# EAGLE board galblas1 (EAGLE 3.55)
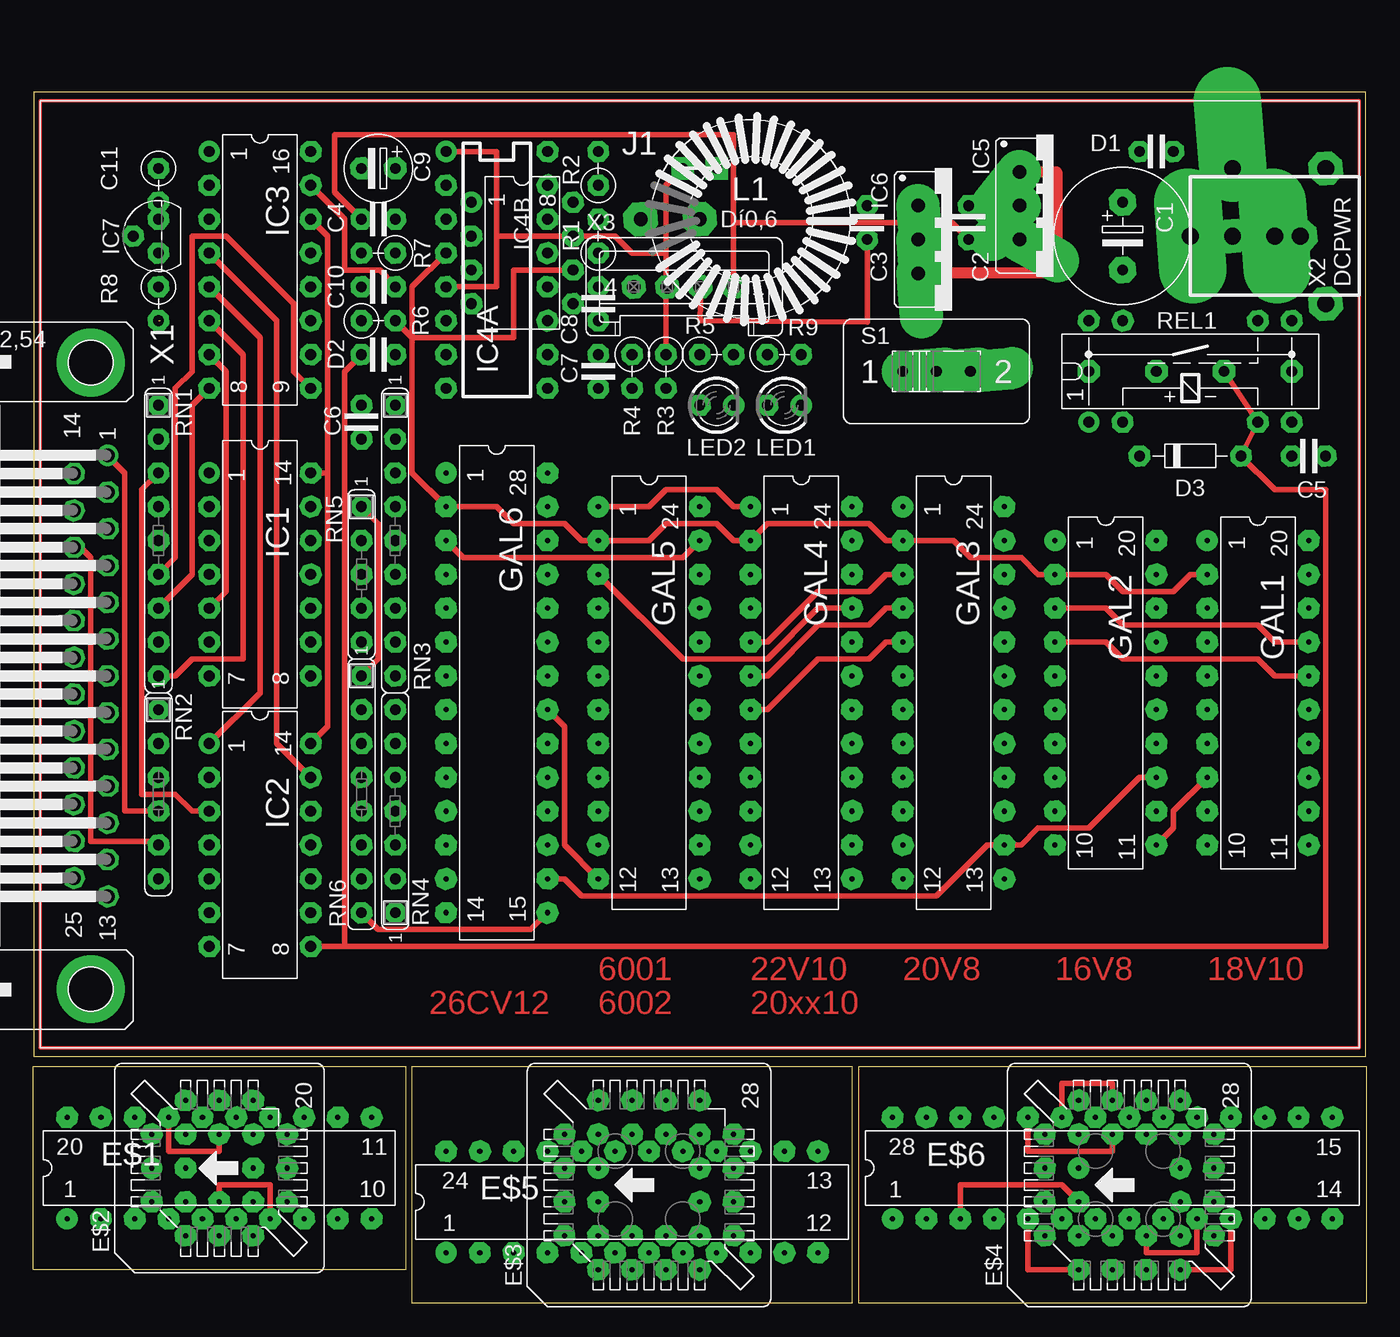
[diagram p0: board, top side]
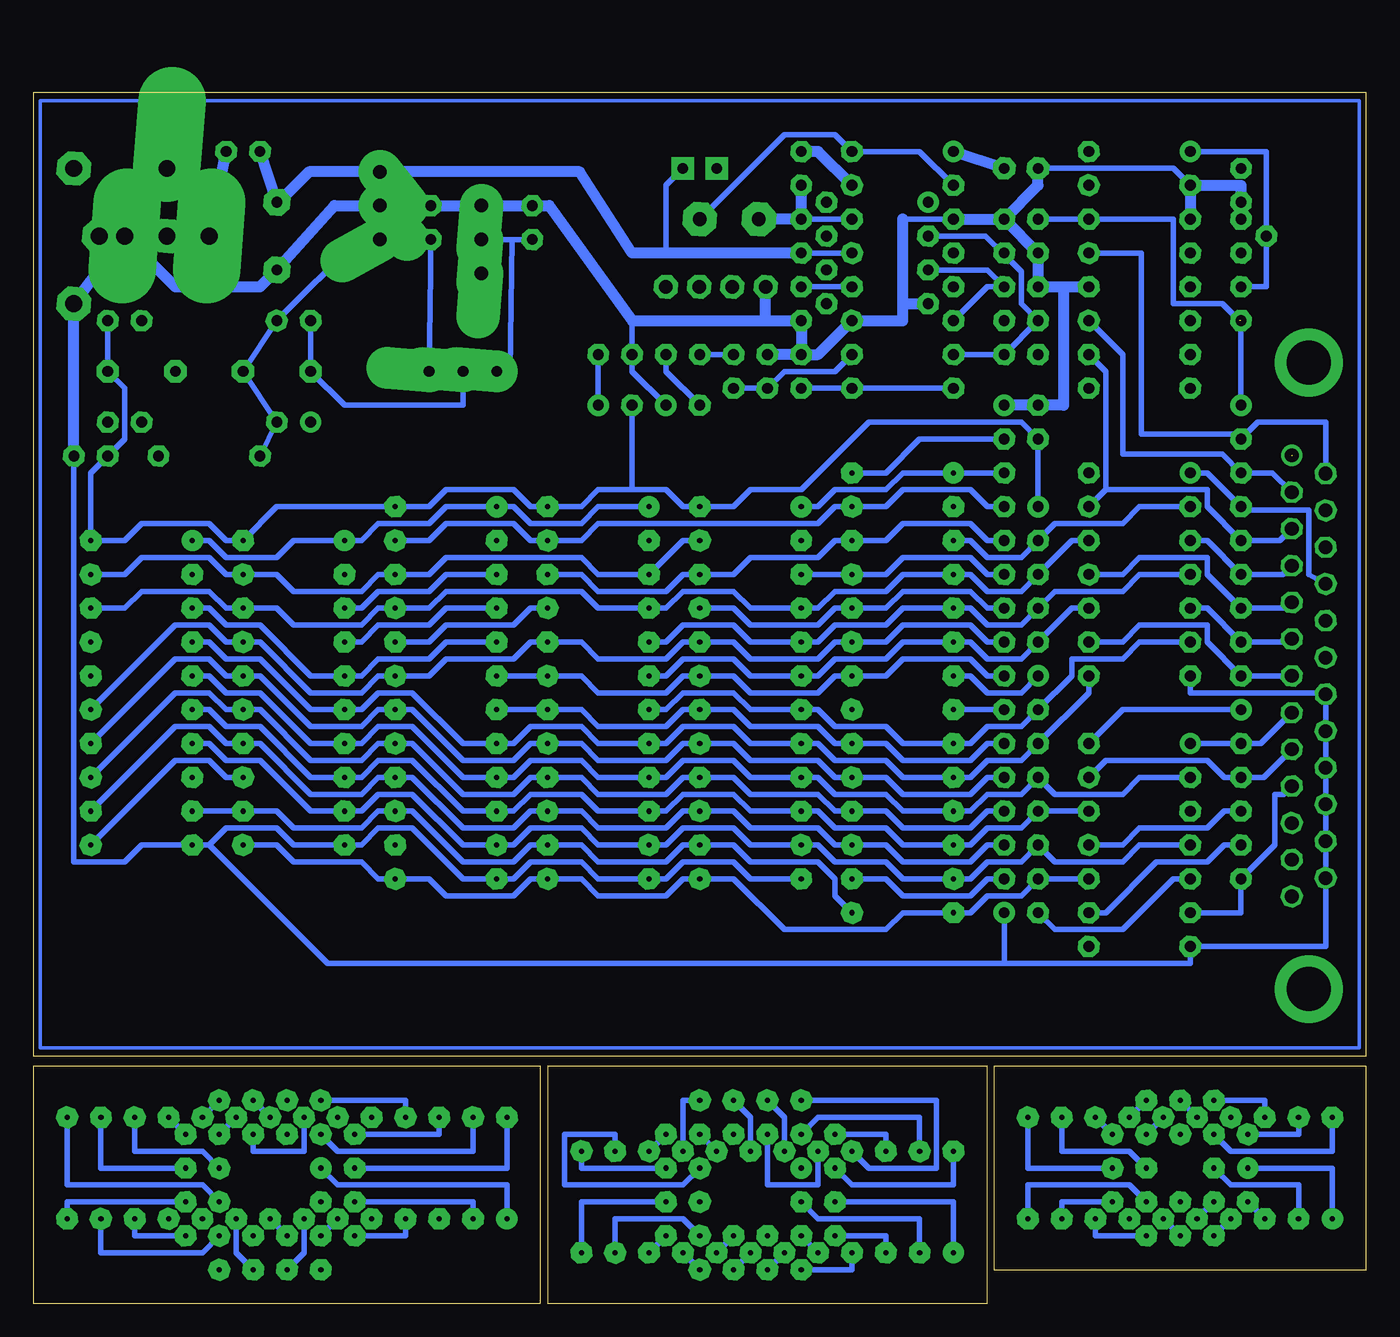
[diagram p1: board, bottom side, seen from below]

Size 100.08 x 90.93 mm. Coordinates in mm from the lower left corner, seen from the top.
Outline: 0.04,18.55 100.04,18.55 100.04,90.93 0.04,90.93 0.04,18.55
Outline: 0,2.54 0,17.78 27.94,17.78 27.94,2.54 0,2.54
Outline: 28.45,0 28.45,17.78 61.47,17.78 61.47,0 28.45,0
Outline: 61.98,0 61.98,17.78 100.08,17.78 100.08,0 61.98,0
Copper layers used: Top, Bottom

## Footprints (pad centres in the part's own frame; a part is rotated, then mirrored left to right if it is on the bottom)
-5 = drill 0.813 pad 2.007 octagon:  -2.54,0;  2.54,0
2,5 = drill 0.813 pad 1.6 octagon:  -1.27,0;  1.27,0
-2,5L = drill 0.813 pad 1.676 octagon:  0,0;  2.54,0
-2,5 = drill 0.813 pad 1.6 octagon:  0,0;  2.54,0
7,5 = drill 0.813 pad 1.6 octagon:  -3.81,0;  3.81,0
L20 = drill 0.381 pad 1.6 round:  -11.43,-3.81 | drill 0.381 pad 1.6 octagon:  -8.89,-3.81;  -6.35,-3.81;  -3.81,-3.81;  -1.27,-3.81;  1.27,-3.81;  3.81,-3.81;  6.35,-3.81;  8.89,-3.81;  11.43,-3.81;  11.43,3.81;  8.89,3.81;  6.35,3.81;  3.81,3.81;  1.27,3.81;  -1.27,3.81;  -3.81,3.81;  -6.35,3.81;  -8.89,3.81;  -11.43,3.81
0 = drill 0.381 pad 1.6 round:  0,5.08 | drill 0.381 pad 1.6 octagon:  0,2.54;  -2.54,5.08;  -5.08,2.54;  -2.54,2.54;  -5.08,0;  -2.54,0;  -5.08,-2.54;  -2.54,-5.08;  -2.54,-2.54;  0,-5.08;  0,-2.54;  2.54,-5.08;  5.08,-2.54;  2.54,-2.54;  5.08,0;  2.54,0;  5.08,2.54;  2.54,5.08;  2.54,2.54
8 = drill 0.381 pad 1.6 round:  1.27,3.81 | drill 0.381 pad 1.6 octagon:  -1.27,6.35;  -1.27,3.81;  -3.81,6.35;  -6.35,3.81;  -3.81,3.81;  -6.35,1.27;  -3.81,1.27;  -6.35,-1.27;  -3.81,-1.27;  -6.35,-3.81;  -3.81,-6.35;  -3.81,-3.81;  -1.27,-6.35;  -1.27,-3.81;  1.27,-6.35;  1.27,-3.81;  3.81,-6.35;  6.35,-3.81;  3.81,-3.81;  6.35,-1.27;  3.81,-1.27;  6.35,1.27;  3.81,1.27;  6.35,3.81;  3.81,6.35;  3.81,3.81;  1.27,6.35
L24-3 = drill 0.381 pad 1.6 round:  -13.97,-3.81 | drill 0.381 pad 1.6 octagon:  -11.43,-3.81;  -8.89,-3.81;  -6.35,-3.81;  -3.81,-3.81;  -1.27,-3.81;  1.27,-3.81;  3.81,-3.81;  6.35,-3.81;  8.89,-3.81;  11.43,-3.81;  13.97,-3.81;  13.97,3.81;  11.43,3.81;  8.89,3.81;  6.35,3.81;  3.81,3.81;  1.27,3.81;  -1.27,3.81;  -3.81,3.81;  -6.35,3.81;  -8.89,3.81;  -11.43,3.81;  -13.97,3.81
L28-3 = drill 0.381 pad 1.6 round:  -16.51,-3.81 | drill 0.381 pad 1.6 octagon:  -13.97,-3.81;  -11.43,-3.81;  -8.89,-3.81;  -6.35,-3.81;  -3.81,-3.81;  -1.27,-3.81;  1.27,-3.81;  3.81,-3.81;  6.35,-3.81;  8.89,-3.81;  11.43,-3.81;  13.97,-3.81;  16.51,-3.81;  16.51,3.81;  13.97,3.81;  11.43,3.81;  8.89,3.81;  6.35,3.81;  3.81,3.81;  1.27,3.81;  -1.27,3.81;  -3.81,3.81;  -6.35,3.81;  -8.89,3.81;  -11.43,3.81;  -13.97,3.81;  -16.51,3.81
L14 = drill 0.813 pad 1.6 round:  -7.62,-3.81 | drill 0.813 pad 1.6 octagon:  -5.08,-3.81;  -2.54,-3.81;  0,-3.81;  2.54,-3.81;  5.08,-3.81;  7.62,-3.81;  7.62,3.81;  5.08,3.81;  2.54,3.81;  0,3.81;  -2.54,3.81;  -5.08,3.81;  -7.62,3.81
L16 = drill 0.813 pad 1.6 round:  -8.89,-3.81 | drill 0.813 pad 1.6 octagon:  -6.35,-3.81;  -3.81,-3.81;  -1.27,-3.81;  1.27,-3.81;  3.81,-3.81;  6.35,-3.81;  8.89,-3.81;  8.89,3.81;  6.35,3.81;  3.81,3.81;  1.27,3.81;  -1.27,3.81;  -3.81,3.81;  -6.35,3.81;  -8.89,3.81
L16' = drill 0.813 pad 1.6 round:  -8.89,-3.81 | drill 0.813 pad 1.6 octagon:  -6.35,-3.81;  -1.27,-3.81;  -3.81,-3.81;  1.27,-3.81;  3.81,-3.81;  6.35,-3.81;  8.89,-3.81;  8.89,3.81;  6.35,3.81;  3.81,3.81;  1.27,3.81;  -1.27,3.81;  -3.81,3.81;  -6.35,3.81;  -8.89,3.81
L08 = drill 0.813 pad 1.6 round:  -3.81,-3.81 | drill 0.813 pad 1.6 octagon:  -1.27,-3.81;  1.27,-3.81;  3.81,-3.81;  3.81,3.81;  1.27,3.81;  -1.27,3.81;  -3.81,3.81
XXS = drill 1.016 pad 3.251 offset:  -2.54,-2.54;  0,-2.54;  2.54,-2.54
220S = drill 1.016 pad 3.251 offset:  -2.54,0;  0,0;  2.54,0
92 = drill 0.813 pad 1.6 octagon:  -1.27,0;  0,1.905;  1.27,0
16 = drill 1.016 pad 2.54 octagon:  -3.81,0;  -8.255,0
D3 = drill 0.813 pad 1.6 octagon:  -1.27,0 | drill 0.813 pad 1.6 round:  1.27,0
1A = drill 0.813 pad 1.6 round:  -7.62,-3.81 | drill 0.813 pad 1.6 octagon:  -5.08,-3.81;  5.08,-3.81;  7.62,-3.81;  7.62,3.81;  5.08,3.81;  -5.08,3.81;  -7.62,3.81
L9 = drill 0.813 pad 1.6 round:  -10.16,0 | drill 0.813 pad 1.6 octagon:  -7.62,0;  -5.08,0;  -2.54,0;  0,0;  2.54,0;  5.08,0;  7.62,0;  10.16,0
L6 = drill 0.813 pad 1.6 round:  -6.35,0 | drill 0.813 pad 1.6 octagon:  -3.81,0;  -1.27,0;  1.27,0;  3.81,0;  6.35,0
L7 = drill 0.813 pad 1.6 round:  -7.62,0 | drill 0.813 pad 1.6 octagon:  -5.08,0;  -2.54,0;  0,0;  2.54,0;  5.08,0;  7.62,0
L5 = drill 0.813 pad 1.6 round:  -5.08,0 | drill 0.813 pad 1.6 octagon:  -2.54,0;  0,0;  2.54,0;  5.08,0
L8 = drill 0.813 pad 1.6 round:  -8.89,0 | drill 0.813 pad 1.6 octagon:  -6.35,0;  -3.81,0;  -1.27,0;  1.27,0;  3.81,0;  6.35,0;  8.89,0
51 = drill 0.813 pad 3.15 offset:  -2.54,0;  0,0;  2.54,0
5HP = drill 1.016 pad 1.6 octagon:  16.561,1.27;  13.792,1.27;  11.049,1.27;  8.28,1.27;  5.512,1.27;  2.769,1.27;  0,1.27;  -2.769,1.27;  -5.512,1.27;  -8.28,1.27;  -11.049,1.27;  -13.792,1.27;  15.189,-1.27;  12.421,-1.27;  9.652,-1.27;  6.909,-1.27;  4.14,-1.27;  1.372,-1.27;  -1.372,-1.27;  -4.14,-1.27;  -6.909,-1.27;  -9.652,-1.27;  -12.421,-1.27;  -15.189,-1.27 | drill 1.016 pad 1.6 round:  -16.561,1.27 | drill 3.302 pad 5.08 round:  -23.52,0;  23.52,0
PWR = drill 1.27 pad 2.54 octagon:  -5.08,-7.62;  5.08,-7.62;  0,-0.635;  0,-5.715 | drill 1.27 pad 5.08 offset:  5.08,-0.635 | drill 1.27 pad 5.08 long:  0,2.54;  0,-3.81
4P = drill 1.016 pad 1.778 octagon:  -4.978,0;  -7.493,0;  -2.489,0;  0,0

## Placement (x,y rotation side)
C1  470u/16V  [-5]  81.79,80.14 270 top
C2  100n  [2,5]  70.23,81.15 270 top
C3  100n  [2,5]  62.61,81.15 270 top
C4  100n  [2,5]  25.91,81.41 180 top
C5  100n  [2,5]  95.76,63.63 180 top
C6  100n  [2,5]  24.64,66.17 270 top
C7  100n  [2,5]  42.42,69.98 90 top
C8  10n  [2,5]  42.42,75.06 270 top
C9  100u/35V  [-2,5L]  27.18,85.22 180 top
C10  4n7  [2,5]  25.91,76.33 180 top
C11  1u/3V  [-2,5]  9.4,85.22 270 top
D1  1N4001  [2,5]  84.33,86.49 180 top
D2  1N4148  [2,5]  25.91,71.25 0 top
D3  1N4148  [7,5]  86.87,63.63 180 top
E$1  [L20]  13.97,10.16 0 top
E$2  [0]  13.97,10.16 90 top
E$3  [8]  46.23,8.89 90 top
E$4  [8]  82.3,8.89 90 top
E$5  [L24-3]  44.96,7.62 0 top
E$6  [L28-3]  81.03,10.16 0 top
GAL1  18V10  [L20]  91.95,45.85 270 top
GAL2  16V8  [L20]  80.52,45.85 270 top
GAL3  20V8  [L24-3]  69.09,45.85 270 top
GAL4  22V10/20xx10  [L24-3]  57.66,45.85 270 top
GAL5  6001/6002  [L24-3]  46.23,45.85 270 top
GAL6  26CV12  [L28-3]  34.8,45.85 270 top
IC1  7417  [L14]  17.02,54.74 270 top
IC2  7417  [L14]  17.02,34.42 270 top
IC3  TLC7524JN  [L16]  17.02,77.6 270 top
IC4A  78S40  [L16']  34.8,77.6 270 top
IC4B  CA3140E  [L08]  36.7,78.87 270 top
IC5  7805  [XXS]  76.58,82.42 270 top
IC6  LD1117V33  [220S]  66.42,79.88 270 top
IC7  LM336Z2.5  [92]  9.4,80.14 90 top
L1  470uH  [16]  53.85,81.41 0 top
LED1  LED3YE  [D3]  56.39,67.44 0 top
LED2  LED3GR  [D3]  51.31,67.44 0 top
R1  1R2  [-2,5]  42.42,78.87 90 top
R2  180R  [-2,5]  42.42,83.95 90 top
R3  220k  [-2,5]  47.5,71.25 270 top
R4  12k  [-2,5]  44.96,71.25 270 top
R5  4k7  [-2,5]  50.04,71.25 0 top
R6  100k  [-2,5]  24.64,73.79 0 top
R7  12k  [-2,5]  27.18,78.87 180 top
R8  390R  [-2,5]  9.4,76.33 270 top
R9  820R  [-2,5]  55.12,71.25 0 top
REL1  RR1A  [1A]  86.87,69.98 0 top
RN1  4k7  [L9]  9.4,57.28 270 top
RN2  4k7  [L6]  9.4,38.23 270 top
RN3  4k7  [L9]  27.18,57.28 270 top
RN4  4k7  [L7]  27.18,36.96 90 top
RN5  4k7  [L5]  24.64,54.74 270 top
RN6  4k7  [L8]  24.64,38.23 270 top
S1  SW1  [51]  67.82,69.98 0 top
X1  M25HP  [5HP]  4.32,47.12 270 top
X2  DCPWR  [PWR]  89.41,80.14 90 top
X3  S04P  [4P]  52.58,76.33 0 top

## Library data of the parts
C1-C11 D1-D3 R1-R9 = DISCRETE
E$1 E$5 E$6 GAL1-GAL6 = DIL
E$2-E$4 = PLCCPACK
IC1 IC2 = 74XX
IC3 IC4B IC7 = LINEAR
IC4A IC5 = V-REG
IC6 = manfred
L1 = IND-A
LED1 LED2 = LED
REL1 = RELAIS
RN1-RN6 = R-SIL
S1 = SWITCH
X1 = SUBD-A
X2 = SPECIAL
X3 = CON-MT

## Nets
/ACK: IC2. RN2. X1.
/STB: GAL1. GAL2. GAL3. GAL4. GAL5. GAL6. IC2. RN6.
/STROBE: IC2. RN2. X1.
D0: IC2. IC3. RN1. X1.
D1: IC1. IC3. RN1. X1.
D2: IC1. IC3. RN1. X1.
D3: IC1. IC3. RN1. X1.
D4: IC1. IC3. RN1. X1.
D5: IC1. IC3. RN1. X1.
D6: IC2. IC3. RN2. X1.
D7: IC2. IC3. RN2. X1.
EDIT: GAL1. GAL2. GAL3. GAL4. GAL5. GAL6. IC4A. IC4B. R6.
N$1: IC3. RN1. X1.
N$2: D1. X2.
N$3: IC1. RN1. X1.
N$4: IC2. RN2. X1.
N$5: C7. IC4A.
N$6: LED2. R5.
N$7: C8. IC4A.
N$8: REL1. S1.
N$9: GAL6. RN4.
N$10: GAL3. GAL4. GAL5. GAL6. RN3.
N$11: IC4A. R3. R4.
N$12: LED1. R9.
N$13: IC4A. L1. R1. R2.
N$14: IC4A. R2.
N$15: GAL5. GAL6. RN3.
N$16: GAL1. GAL2. GAL3. GAL4. GAL5. GAL6. RN3.
N$17: IC4A. L1.
N$18: C9. IC4A. IC4B. R3. R5. X3.
N$19: C1. C2. C3. C4. C5. C6. C7. C8. C9. C10. C11. GAL1. GAL2. GAL3. GAL4. GAL5. GAL6. IC1. IC2. IC3. IC4A. IC4B. IC5. IC6. IC7. LED2. R4. R7. R9. RN3. RN4. X1. X2. X3.
N$20: C1. D1. IC4A. IC5. IC6. R1.
N$21: C11. IC3. IC7. R8.
N$22: GAL3. GAL4. GAL5. GAL6. RN3.
N$23: D2. IC4A. IC4B. R6. R7.
N$24: GAL3. GAL4. GAL5. GAL6. RN4.
N$25: GAL1. GAL2. GAL3. GAL4. GAL5. GAL6. RN4.
N$26: GAL1. GAL2. GAL3. GAL4. GAL5. GAL6. RN4.
N$27: C2. C4. D3. IC1. IC2. IC3. IC5. R8. REL1. RN1. RN2. S1. X3.
N$28: GAL1. GAL2. GAL3. GAL4. GAL5. GAL6. RN4.
N$29: GAL1. GAL2. GAL3. GAL6. RN4.
N$30: GAL6. RN3.
N$31: GAL1. GAL2. GAL3. GAL4. GAL5. GAL6. RN3.
N$32: GAL4. GAL5. GAL6. RN3.
N$33: GAL3. GAL4. GAL6. RN3.
N$35: C10. IC3. IC4A. IC4B.
N$39: D2. D3. IC2. REL1.
P/V: GAL1. GAL2. GAL3. GAL4. GAL5. GAL6. IC1. RN5.
RA0: GAL1. GAL2. GAL3. GAL4. GAL5. GAL6. IC1. RN5.
RA1: GAL1. GAL2. GAL3. GAL4. GAL5. GAL6. IC1. RN5.
RA2: GAL1. GAL2. GAL3. GAL4. GAL5. GAL6. IC1. RN5.
RA3: GAL1. GAL2. GAL3. GAL4. GAL5. GAL6. IC1. RN6.
RA4: GAL1. GAL2. GAL3. GAL4. GAL5. GAL6. IC1. RN6.
RA5: GAL1. GAL2. GAL3. GAL4. GAL5. GAL6. IC2. RN6.
S$1: E$1. E$2.
S$2: E$1. E$2.
S$3: E$1. E$2.
S$4: E$1. E$2.
S$5: E$1. E$2.
S$6: E$1. E$2.
S$7: E$1. E$2.
S$8: E$4. E$6.
S$9: E$4. E$6.
S$10: E$1. E$2.
S$11: E$1. E$2.
S$12: E$1. E$2.
S$13: E$1. E$2.
S$14: E$1. E$2.
S$15: E$1. E$2.
S$16: E$1. E$2.
S$17: E$1. E$2.
S$18: E$1. E$2.
S$19: E$1. E$2.
S$20: E$1. E$2.
S$21: E$1. E$2.
S$22: E$1. E$2.
S$24: E$4. E$6.
S$25: E$4. E$6.
S$26: E$4. E$6.
S$27: E$4. E$6.
S$28: E$4. E$6.
S$29: E$4. E$6.
S$30: E$4. E$6.
S$31: E$4. E$6.
S$32: E$4. E$6.
S$33: E$4. E$6.
S$34: E$4. E$6.
S$35: E$4. E$6.
S$36: E$4. E$6.
S$37: E$4. E$6.
S$38: E$4. E$6.
S$39: E$4. E$6.
S$40: E$4. E$6.
S$41: E$4. E$6.
S$42: E$3. E$5.
S$43: E$3. E$5.
S$44: E$3. E$5.
S$45: E$3. E$5.
S$46: E$3. E$5.
S$47: E$3. E$5.
S$48: E$3. E$5.
S$49: E$3. E$5.
S$50: E$3. E$5.
S$51: E$3. E$5.
S$52: E$3. E$5.
S$53: E$3. E$5.
S$54: E$3. E$5.
S$55: E$3. E$5.
S$56: E$3. E$5.
S$57: E$3. E$5.
S$58: E$3. E$5.
S$59: E$3. E$5.
S$60: E$3. E$5.
S$61: E$3. E$5.
S$62: E$3. E$5.
S$63: E$3. E$5.
S$64: E$3. E$5.
S$65: E$3. E$5.
S$66: E$4. E$6.
S$67: E$4. E$6.
S$68: E$4. E$6.
S$69: E$4. E$6.
S$70: E$4. E$6.
S$71: E$4. E$6.
S$72: E$4. E$6.
S$73: E$4. E$6.
SCHALT: X2.
SCLK: GAL1. GAL2. GAL3. GAL4. GAL5. GAL6. IC2. RN6.
SDIN: GAL1. GAL2. GAL3. GAL4. GAL5. GAL6. IC2. RN6.
SDOUT: GAL1. GAL2. GAL3. GAL4. GAL5. GAL6. IC2. RN6.
SW1: C3. IC6. S1. X3.
VCC: C5. C6. GAL1. GAL2. GAL3. GAL4. GAL5. GAL6. LED1. REL1. RN5. RN6.

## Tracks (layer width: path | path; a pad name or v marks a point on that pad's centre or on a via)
/ACK
  Bottom 0.406: 5.59,38.84 6.2,38.23 6.86,38.23 6.86,34.42 RN2. 9.4,29.34 13.21,29.34
/STB
  Top 0.406: 88.14,39.5 85.6,36.96 85.6,35.69 84.33,34.42
  Bottom 0.406: 84.33,34.42 81.79,34.42 80.52,33.15 75.44,33.15 74.17,31.88 72.9,31.88 70.36,31.88 69.09,30.61 64.01,30.61 62.74,31.88 61.47,31.88 58.93,31.88 57.66,30.61 52.58,30.61 51.31,31.88 50.04,31.88 47.5,31.88 43.69,28.07 36.07,28.07 34.8,29.34 30.99,29.34 29.72,29.34 28.45,30.61 25.91,30.61 24.64,31.88 20.83,31.88
/STROBE  (1 unrouted)
  Top 0.406: 5.59,63.63 6.86,62.36 6.86,36.96 9.4,36.96
  Bottom 0.406: 9.4,36.96 10.67,36.96 11.94,35.69 17.02,35.69 18.29,34.42 20.83,34.42
D0
  Top 0.406: 9.4,62.36 8.13,61.09 8.13,38.23 10.67,38.23 11.94,36.96 13.21,36.96
  Bottom 0.406: 5.59,60.91 7.04,62.36 9.4,62.36 10.8,63.75 18.29,63.75 18.29,71.25 20.83,73.79
D1
  Bottom 0.406: 5.59,58.17 6.48,57.28 9.4,57.28 11.94,59.82 11.94,61.09 19.56,61.09 | 19.56,61.09 20.83,59.82 | 19.56,61.09 19.56,69.98 20.83,71.25
D2
  Top 0.406: 20.83,68.71 19.56,69.98 19.56,75.06 14.48,80.14 11.94,80.14 11.94,69.98 10.67,68.71 10.67,56.01 9.4,54.74
  Bottom 0.406: 5.59,55.4 6.25,54.74 9.4,54.74 11.94,57.28 13.21,57.28
D3
  Top 0.406: 13.21,68.71 11.94,67.44 11.94,54.74 9.4,52.2
  Bottom 0.406: 5.59,52.63 6.02,52.2 9.4,52.2 11.94,54.74 11.94,56.01 17.02,56.01 18.29,54.74 20.83,54.74
D4
  Top 0.406: 13.21,71.25 14.48,69.98 14.48,53.47 13.21,52.2
  Bottom 0.406: 5.59,49.89 5.82,49.66 9.4,49.66 11.94,52.2 13.21,52.2
D5
  Top 0.406: 13.21,73.79 15.75,71.25 15.75,48.39 11.94,48.39 10.67,47.12 RN1.
  Bottom 0.406: 5.59,47.12 RN1. 11.94,49.66 11.94,50.93 17.02,50.93 18.29,49.66 20.83,49.66
D6
  Top 0.406: 13.21,76.33 17.02,72.52 17.02,45.85 13.21,42.04
  Bottom 0.406: 5.59,44.35 7.9,42.04 9.4,42.04 13.21,42.04
D7
  Top 0.406: 13.21,78.87 18.29,73.79 18.29,42.04 20.83,39.5
  Bottom 0.406: 5.59,41.61 7.7,39.5 9.4,39.5 10.67,39.5 11.94,40.77 19.56,40.77 20.83,39.5
EDIT
  Top 0.406: 88.14,54.74 86.87,54.74 85.6,53.47 81.79,53.47 80.52,54.74 76.71,54.74 75.44,54.74 74.17,56.01 70.36,56.01 69.09,57.28 65.28,57.28 64.01,57.28 62.74,58.55 55.12,58.55 53.85,57.28 52.58,57.28 51.31,58.55 47.5,58.55 46.23,57.28 42.42,57.28 41.15,57.28 39.88,58.55 36.07,58.55 34.8,59.82 30.99,59.82 28.45,62.36 28.45,72.52 | 40.51,77.6 36.07,77.6 36.07,72.52 28.45,72.52 | 28.45,72.52 R6. | 30.99,78.87 28.45,76.33 28.45,72.52
N$1
  Bottom 0.406: 3.05,62.31 3.05,66.17 8.13,66.17 9.4,64.9 9.78,65.28 16.89,65.28 16.89,78.87 20.83,78.87
N$2
  Bottom 0.813: 85.6,86.49 86.87,80.14 89.41,80.14
N$3
  Bottom 0.406: 3.05,54.03 4.32,54.74 4.32,59.56 9.14,59.56 9.4,59.82 11.94,62.36 13.21,62.36
N$4
  Top 0.406: 3.05,56.77 3.56,56.77 4.32,56.01 4.32,34.67 9.14,34.67 9.4,34.42
  Bottom 0.406: 9.4,34.42 10.67,34.42 11.94,33.15 15.75,33.15 19.56,29.34 20.83,29.34
N$5
  Bottom 0.406: 30.99,68.71 38.61,68.71 42.42,68.71
N$6
  Bottom 0.406: 50.04,67.44 52.58,69.98 R5.
N$7
  Bottom 0.406: 38.61,76.33 42.42,76.33
N$8  (via drill 0.81 pad 1.68)
  Bottom 0.406: 67.82,69.98 67.82,67.44 76.71,67.44 v79.25,69.98 REL1.
N$9
  Bottom 0.406: RN4. 30.99,44.58
N$10
  Top 0.406: 61.47,52.2 58.93,52.2 55.12,48.39 48.77,48.39 42.42,54.74
  Bottom 0.406: 42.42,54.74 38.61,54.74 36.07,54.74 34.8,56.01 29.72,56.01 28.45,54.74 27.18,54.74 | 61.47,52.2 62.74,52.2 64.01,50.93 69.09,50.93 70.36,49.66 72.9,49.66
N$11
  Bottom 0.406: 38.61,71.25 39.88,69.98 43.69,69.98 R4. R3.
N$12
  Bottom 0.406: LED1. R9.
N$13
  Bottom 0.406: 38.61,81.41 R1.
  Bottom 0.813: 42.42,83.95 R1. L1.
N$14
  Bottom 0.813: 38.61,83.95 41.15,86.49 R2.
N$15
  Bottom 0.406: 50.04,52.2 47.5,52.2 46.23,50.93 41.15,50.93 39.88,52.2 38.61,52.2 36.07,52.2 34.8,53.47 29.72,53.47 28.45,52.2 27.18,52.2
N$16
  Bottom 0.406: 27.18,49.66 28.45,49.66 29.72,50.93 34.8,50.93 36.07,49.66 38.61,49.66 39.88,49.66 41.15,48.39 46.23,48.39 47.5,49.66 50.04,49.66 51.31,49.66 52.58,48.39 57.66,48.39 58.93,49.66 61.47,49.66 62.74,49.66 64.01,48.39 69.09,48.39 70.36,47.12 72.9,47.12 74.17,47.12 75.44,45.85 79.25,45.85 83.06,49.66 84.33,49.66 85.6,49.66 86.87,50.93 89.41,50.93 95.76,44.58
N$17
  Bottom 0.406: 30.99,83.95 33.53,86.49 IC4A. 39.88,87.76 43.69,87.76 50.04,81.41
N$18  (via drill 0.81 pad 1.68)
  Top 0.406: 47.5,76.33 47.5,71.25 | 47.5,76.33 47.6,76.33 | 47.5,78.87 47.5,76.33 | 47.5,78.87 44.96,78.87 43.69,80.14 40.51,80.14 34.8,80.14 | 34.8,80.14 34.8,86.49 30.99,86.49 | 47.5,78.87 47.5,83.95 v48.77,85.22 | 30.99,76.33 34.8,76.33 34.8,80.14
  Bottom 0.406: 47.5,71.25 50.04,71.25
  Bottom 0.813: 30.99,86.49 27.18,85.22
N$19
  Top 0.406: 38.61,44.58 39.88,43.31 39.88,34.42 42.42,31.88
  Bottom 0.406: 42.42,31.88 46.23,31.88 47.5,33.15 51.31,33.15 52.58,31.88 53.85,31.88 57.66,31.88 58.93,33.15 62.74,33.15 64.01,31.88 65.28,31.88 67.82,31.88 71.63,35.69 74.17,35.69 75.44,34.42 76.71,34.42 80.52,34.42 81.79,35.69 85.6,35.69 86.87,34.42 | 24.64,67.44 27.18,67.44 | 86.87,34.42 88.14,34.42 91.95,34.42 93.22,33.15 97.03,33.15 97.03,63.63 | 27.18,25.53 13.21,25.53 13.21,26.8 3.05,26.8 3.05,31.93 3.05,34.7 3.05,36.96 | 13.21,47.12 13.21,45.85 3.05,45.85 3.05,45.74 3.05,42.98 3.05,40.21 | 27.18,25.53 27.18,29.34 | 27.18,25.53 77.98,25.53 86.87,34.42 | 34.8,81.41 30.99,81.41 | 55.12,73.79 55.12,71.25 55.12,69.98 LED2. | 3.05,36.96 3.05,37.47 3.05,39.5 | 3.05,40.21 3.05,40.77 | 3.05,39.5 3.05,40.21 | 3.05,36.96 3.05,39.5 | 3.05,36.96 3.05,40.21 | 13.21,83.95 14.48,85.22 C9. | C8. C7. C8.
  Bottom 0.813: 70.23,82.42 74.04,82.42 70.23,82.42 | 70.23,82.42 77.47,82.42 C1. 83.06,76.33 89.41,76.33 93.22,80.14 97.03,75.06 97.03,63.63 | C7. 41.15,71.25 38.61,73.79 34.8,73.79 34.8,75.06 | 34.8,75.06 34.8,81.41 | C7. C8. 44.96,73.79 | C7. 44.96,71.25 | 27.18,67.44 24.64,67.44 22.73,67.44 22.73,76.33 | 44.96,73.79 55.12,73.79 61.34,82.42 62.61,82.42 66.42,82.42 70.23,82.42 | 45.09,76.33 45.09,73.91 44.96,73.79 | 13.21,81.41 13.21,83.95 9.4,83.95 IC7. | 34.8,75.06 32.89,75.06 | 30.99,81.41 27.18,81.41 | 22.73,76.33 C10. R7. 27.18,81.41 | 27.18,81.41 24.64,83.95 C9. | 22.73,76.33 20.83,76.33
N$20  (via drill 0.81 pad 1.68)
  Top 0.813: IC6. 76.83,77.34 76.83,84.96 74.04,84.96
  Bottom 0.406: 38.61,78.87 42.42,78.87 | 52.58,78.87 52.58,83.95 v51.31,85.22
  Bottom 0.813: 42.42,78.87 52.58,78.87 55.12,78.87 59.05,84.96 74.04,84.96 79.38,84.96 81.66,82.68 81.79,82.68 D1.
N$21
  Bottom 0.406: 13.21,86.49 9.4,86.49 7.49,86.49 7.49,80.14 7.49,76.33 9.4,76.33
N$22
  Bottom 0.406: 65.28,47.12 61.47,47.12 58.93,47.12 57.66,45.85 52.58,45.85 51.31,47.12 50.04,47.12 47.5,47.12 46.23,45.85 41.15,45.85 39.88,47.12 38.61,47.12 36.07,47.12 34.8,48.39 29.72,48.39 28.45,47.12 RN3.
N$23
  Bottom 0.406: 30.99,71.25 D2. 24.64,73.79 25.91,75.06 25.91,77.47 27.18,78.74 | 27.18,78.74 27.18,78.87 | 32.89,80.14 28.57,80.14 27.18,78.74
N$24
  Bottom 0.406: 65.28,44.58 61.47,44.58 58.93,44.58 57.66,43.31 52.58,43.31 51.31,44.58 50.04,44.58 47.5,44.58 46.23,43.31 41.15,43.31 39.88,42.04 38.61,42.04 36.07,42.04 34.8,40.77 29.72,40.77 28.45,42.04 27.18,42.04
N$25
  Bottom 0.406: 27.18,39.5 28.45,39.5 29.72,38.23 34.8,38.23 36.07,39.5 38.61,39.5 39.88,39.5 41.15,40.77 46.23,40.77 47.5,42.04 50.04,42.04 51.31,42.04 52.58,40.77 57.66,40.77 58.93,42.04 61.47,42.04 62.74,42.04 64.01,40.77 67.82,40.77 71.63,44.58 72.9,44.58 74.17,44.58 75.44,43.31 79.25,43.31 83.06,47.12 84.33,47.12 85.6,47.12 86.87,48.39 89.41,48.39 95.76,42.04
N$26
  Bottom 0.406: 27.18,36.96 28.45,36.96 29.72,35.69 34.8,35.69 36.07,36.96 38.61,36.96 39.88,36.96 41.15,38.23 46.23,38.23 47.5,39.5 50.04,39.5 51.31,39.5 52.58,38.23 57.66,38.23 58.93,39.5 61.47,39.5 62.74,39.5 64.01,38.23 67.82,38.23 71.63,42.04 72.9,42.04 74.17,42.04 75.44,40.77 79.25,40.77 83.06,44.58 84.33,44.58 85.6,44.58 86.87,45.85 89.41,45.85 95.76,39.5
N$27  (via drill 0.81 pad 1.68)  (1 unrouted)
  Top 0.406: C4. 22.61,83.44 22.61,87.76 52.58,87.76 52.58,81.15 | 52.58,81.15 X3. | C2. 68.96,81.15 52.58,81.15 | 22.1,62.36 22.1,43.31 IC2. | 22.1,62.36 IC1. | 22.1,62.36 22.1,80.14 20.83,81.41
  Bottom 0.406: 9.52,73.79 10.8,75.06 14.48,75.06 14.48,81.41 20.83,81.41 C4. | IC2. 18.29,44.58 9.4,44.58 | C2. IC5. | C2. 70.23,77.34 S1. | C2. IC5. | D3. 81.79,66.17 v84.33,69.98 81.79,73.79 75.69,79.88 IC5. | 9.4,67.44 R8.
N$28
  Bottom 0.406: 27.18,34.42 28.45,34.42 29.72,33.15 34.8,33.15 36.07,34.42 38.61,34.42 39.88,34.42 41.15,35.69 46.23,35.69 47.5,36.96 50.04,36.96 51.31,36.96 52.58,35.69 57.66,35.69 58.93,36.96 61.47,36.96 62.74,36.96 64.01,35.69 67.82,35.69 71.63,39.5 72.9,39.5 74.17,39.5 75.44,38.23 79.25,38.23 83.06,42.04 84.33,42.04 85.6,42.04 86.87,43.31 89.41,43.31 95.76,36.96
N$29
  Top 0.406: 38.61,31.88 39.88,31.88 41.15,30.61 67.82,30.61 71.63,34.42 72.9,34.42 74.17,34.42 75.44,35.69 79.25,35.69 83.06,39.5 84.33,39.5
  Bottom 0.406: 38.61,31.88 36.07,31.88 34.8,30.61 29.72,30.61 28.45,31.88 27.18,31.88 | 95.76,34.42 89.41,40.77 86.87,40.77 85.6,39.5 84.33,39.5
N$30
  Bottom 0.406: GAL6. 36.07,62.36 33.53,64.9 27.18,64.9
N$31
  Top 0.406: 42.42,59.82 46.23,59.82 47.5,61.09 51.31,61.09 52.58,59.82 53.85,59.82
  Bottom 0.406: 42.42,59.82 41.15,59.82 39.88,61.09 36.07,61.09 34.8,62.36 30.99,62.36 27.18,62.36 | 88.14,57.28 86.87,57.28 85.6,56.01 81.79,56.01 80.52,57.28 76.71,57.28 75.44,57.28 74.17,58.55 70.36,58.55 69.09,59.82 65.28,59.82 64.01,59.82 62.74,58.55 58.93,58.55 57.66,59.82 53.85,59.82
N$32
  Bottom 0.406: 61.47,54.74 58.93,54.74 57.66,53.47 52.58,53.47 51.31,54.74 50.04,54.74 47.5,54.74 46.23,56.01 41.15,56.01 39.88,57.28 38.61,57.28 36.07,57.28 34.8,58.55 29.72,58.55 28.45,57.28 27.18,57.28
N$33
  Bottom 0.406: 72.9,57.28 70.36,57.28 69.09,58.55 64.01,58.55 62.74,57.28 61.47,57.28 58.93,57.28 57.66,58.55 41.15,58.55 39.88,59.82 38.61,59.82 36.07,59.82 34.8,61.09 29.72,61.09 28.45,59.82 27.18,59.82
N$34
  Top 0.254: 0.51,90.3 99.57,90.3 99.57,19.18 0.51,19.18 0.51,90.3
N$35
  Top 0.406: 20.83,83.95 23.37,81.41 23.37,77.6 26.04,77.6 26.42,77.22 27.18,76.33
  Bottom 0.406: 32.89,77.6 28.45,77.6 27.18,76.33 28.45,76.33 30.99,73.79
N$37
  Bottom 0.254: 0.51,90.3 99.57,90.3 99.57,19.18 0.51,19.18 0.51,90.3
N$38  (via drill 0.81 pad 1.68)
  other vias: 94.49,69.98
N$39  (via drill 0.81 pad 1.68)
  Top 0.406: 20.83,26.8 23.37,26.8 | 23.37,26.8 23.37,69.98 24.64,71.25 | 23.37,26.8 97.03,26.8 97.03,61.09 93.22,61.09 90.68,63.63 91.95,66.17 v89.41,69.98
P/V
  Top 0.406: 50.04,57.28 48.77,56.01 32.26,56.01 30.99,57.28
  Bottom 0.406: 50.04,57.28 51.31,57.28 53.85,54.74 57.66,54.74 58.93,56.01 69.09,56.01 70.36,54.74 72.9,54.74 74.17,54.74 75.44,53.47 80.52,53.47 81.79,54.74 84.33,54.74 85.6,54.74 86.87,56.01 91.95,56.01 93.22,54.74 95.76,54.74 | 30.99,57.28 29.72,57.28 28.45,56.01 25.91,56.01 24.64,57.28 23.37,58.55 18.29,58.55 17.02,59.82 13.21,59.82
RA0
  Bottom 0.406: 95.76,52.2 93.22,52.2 91.95,53.47 86.87,53.47 85.6,52.2 84.33,52.2 81.79,52.2 80.52,50.93 75.44,50.93 74.17,52.2 72.9,52.2 70.36,52.2 69.09,53.47 58.93,53.47 57.66,52.2 53.85,52.2 52.58,52.2 51.31,53.47 47.5,53.47 46.23,52.2 42.42,52.2 41.15,52.2 39.88,53.47 36.07,53.47 34.8,54.74 30.99,54.74 29.72,54.74 28.45,53.47 25.91,53.47 24.64,54.74 22.1,57.28 20.83,57.28
RA1
  Top 0.406: 76.71,52.2 80.52,52.2 81.79,50.93 91.95,50.93 93.22,49.66 95.76,49.66 | 53.85,49.66 55.12,49.66 58.93,53.47 62.74,53.47 64.01,54.74 65.28,54.74
  Bottom 0.406: 53.85,49.66 52.58,49.66 51.31,50.93 47.5,50.93 46.23,49.66 42.42,49.66 41.15,49.66 39.88,50.93 36.07,50.93 34.8,52.2 30.99,52.2 29.72,52.2 28.45,50.93 25.91,50.93 24.64,52.2 23.37,53.47 18.29,53.47 17.02,54.74 13.21,54.74 | 65.28,54.74 69.09,54.74 70.36,53.47 74.17,53.47 75.44,52.2 76.71,52.2
RA2
  Top 0.406: 76.71,49.66 80.52,49.66 81.79,48.39 91.95,48.39 93.22,47.12 95.76,47.12 | 53.85,47.12 55.12,47.12 58.93,50.93 62.74,50.93 64.01,52.2 65.28,52.2
  Bottom 0.406: 53.85,47.12 52.58,47.12 51.31,48.39 47.5,48.39 46.23,47.12 42.42,47.12 41.15,47.12 39.88,48.39 36.07,48.39 34.8,49.66 30.99,49.66 29.72,49.66 28.45,48.39 25.91,48.39 RN5. 22.1,52.2 20.83,52.2 | 65.28,52.2 69.09,52.2 70.36,50.93 74.17,50.93 75.44,49.66 76.71,49.66
RA3
  Top 0.406: 53.85,44.58 55.12,44.58 58.93,48.39 62.74,48.39 64.01,49.66 65.28,49.66
  Bottom 0.406: 53.85,44.58 52.58,44.58 51.31,45.85 47.5,45.85 46.23,44.58 42.42,44.58 41.15,44.58 39.88,43.31 36.07,43.31 34.8,42.04 30.99,42.04 29.72,42.04 28.45,43.31 25.91,43.31 24.64,44.58 22.1,47.12 22.1,48.39 18.29,48.39 17.02,49.66 13.21,49.66 | 88.14,52.2 86.87,52.2 85.6,50.93 83.06,50.93 79.25,47.12 76.71,47.12 75.44,47.12 74.17,48.39 70.36,48.39 69.09,49.66 65.28,49.66
RA4
  Bottom 0.406: 88.14,49.66 86.87,49.66 85.6,48.39 83.06,48.39 79.25,44.58 76.71,44.58 75.44,44.58 74.17,45.85 71.63,45.85 67.82,42.04 65.28,42.04 64.01,42.04 62.74,43.31 58.93,43.31 57.66,42.04 53.85,42.04 52.58,42.04 51.31,43.31 47.5,43.31 46.23,42.04 42.42,42.04 41.15,42.04 39.88,40.77 36.07,40.77 34.8,39.5 30.99,39.5 29.72,39.5 28.45,40.77 25.91,40.77 24.64,42.04 20.83,45.85 20.83,47.12
RA5
  Bottom 0.406: 88.14,47.12 86.87,47.12 85.6,45.85 83.06,45.85 79.25,42.04 76.71,42.04 75.44,42.04 74.17,43.31 71.63,43.31 67.82,39.5 65.28,39.5 64.01,39.5 62.74,40.77 58.93,40.77 57.66,39.5 53.85,39.5 52.58,39.5 51.31,40.77 47.5,40.77 46.23,39.5 42.42,39.5 41.15,39.5 39.88,38.23 36.07,38.23 34.8,36.96 30.99,36.96 29.72,36.96 28.45,38.23 25.91,38.23 24.64,39.5 23.37,38.23 18.29,38.23 17.02,39.5 13.21,39.5
S$1
  Bottom 0.406: 8.89,10.16 2.54,10.16 2.54,6.35
S$2
  Bottom 0.406: 11.43,10.16 10.16,8.89 5.08,8.89 5.08,6.35
S$3
  Bottom 0.406: 8.89,7.62 7.62,6.35
S$4
  Bottom 0.406: 11.43,5.08 10.16,6.35
S$5
  Bottom 0.406: 11.43,7.62 12.7,6.35
S$6
  Bottom 0.406: 13.97,5.08 15.24,6.35
S$7
  Bottom 0.406: 16.51,5.08 20.32,5.08 20.32,6.35
S$8
  Bottom 0.406: 78.49,10.16 77.22,8.89 64.52,8.89 64.52,6.35
S$9
  Bottom 0.406: 75.95,7.62 67.06,7.62 67.06,6.35
S$10
  Bottom 0.406: 19.05,10.16 25.4,10.16 25.4,13.97
S$11
  Bottom 0.406: 16.51,10.16 17.78,11.43 22.86,11.43 22.86,13.97
S$12
  Bottom 0.406: 19.05,12.7 20.32,13.97
S$13
  Bottom 0.406: 17.78,13.97 16.51,15.24
S$14
  Bottom 0.406: 15.24,13.97 16.51,12.7
S$15
  Bottom 0.406: 12.7,13.97 13.97,15.24
S$16
  Bottom 0.406: 11.43,15.24 7.62,15.24 7.62,13.97
S$17
  Bottom 0.406: E$2. 10.16,11.43 2.54,11.43 E$1.
S$18
  Bottom 0.406: 8.89,12.7 5.08,12.7 5.08,13.97
S$19
  Bottom 0.406: 19.05,7.62 22.86,7.62 22.86,6.35
S$20
  Bottom 0.406: 16.51,7.62 17.78,8.89 25.4,8.89 25.4,6.35
S$21
  Top 0.406: 17.78,6.35 17.78,8.89 13.97,8.89 13.97,7.62
S$22
  Top 0.406: 13.97,12.7 13.97,11.43 10.16,11.43 10.16,13.97
S$23
  Bottom 0: 0,2.54 0,17.78 27.94,17.78 27.94,2.54 0,2.54
S$24
  Bottom 0.406: 75.95,5.08 72.14,5.08 72.14,6.35
S$25
  Bottom 0.406: 78.49,5.08 77.22,6.35
S$26
  Bottom 0.406: 81.03,2.54 79.76,3.81 79.76,6.35
S$27
  Bottom 0.406: 81.03,5.08 82.3,6.35
S$28
  Bottom 0.406: 83.57,2.54 84.84,3.81 84.84,6.35
S$29
  Top 0.406: 86.11,2.54 89.92,2.54 89.92,6.35
S$30
  Bottom 0.406: 88.65,5.08 92.46,5.08 92.46,6.35
S$31
  Bottom 0.406: 86.11,5.08 87.38,3.81 95,3.81 95,6.35
S$32
  Bottom 0.406: 88.65,7.62 97.54,7.62 97.54,6.35
S$33
  Bottom 0.406: 86.11,7.62 87.38,8.89 97.54,8.89 97.54,13.97
S$34
  Bottom 0.406: 88.65,10.16 95,10.16 95,13.97
S$35
  Bottom 0.406: 86.11,10.16 87.38,11.43 92.46,11.43 92.46,13.97
S$36
  Bottom 0.406: 88.65,12.7 89.92,13.97
S$37
  Bottom 0.406: 86.11,12.7 84.84,13.97
S$38
  Bottom 0.406: 86.11,15.24 87.38,13.97
S$39
  Bottom 0.406: 67.06,13.97 67.06,11.43 77.22,11.43 78.49,12.7
S$40
  Bottom 0.406: 69.6,13.97 69.6,12.7 75.95,12.7
S$41
  Bottom 0.406: E$4. 64.52,10.16 E$6.
S$42
  Bottom 0.406: 39.88,7.62 30.99,7.62 30.99,3.81
S$43
  Bottom 0.406: 42.42,7.62 41.15,6.35 33.53,6.35 33.53,3.81
S$44
  Bottom 0.406: 39.88,5.08 36.07,5.08 36.07,3.81
S$45
  Bottom 0.406: 42.42,2.54 38.61,2.54 38.61,3.81
S$46
  Bottom 0.406: 42.42,5.08 41.15,3.81
S$47
  Bottom 0.406: 44.96,2.54 43.69,3.81
S$48
  Bottom 0.406: 52.58,10.16 58.93,10.16 58.93,11.43
S$49
  Bottom 0.406: 52.58,12.7 53.85,11.43
S$50
  Bottom 0.406: 50.04,15.24 51.31,15.24 51.31,11.43
S$51
  Bottom 0.406: 50.04,12.7 48.77,11.43
S$52
  Bottom 0.406: 47.5,15.24 46.23,13.97 46.23,11.43
S$53
  Bottom 0.406: 47.5,2.54 46.23,3.81
S$54
  Bottom 0.406: 48.77,3.81 47.5,5.08
S$55
  Bottom 0.406: 50.04,2.54 51.31,3.81
S$56
  Bottom 0.406: 53.85,3.81 52.58,5.08
S$57
  Bottom 0.406: 56.39,3.81 56.39,6.35 51.31,6.35 50.04,5.08
S$58
  Bottom 0.406: 58.93,3.81 58.93,7.62 52.58,7.62
S$59
  Bottom 0.406: E$3. 38.61,8.89 30.99,8.89 E$5.
S$60
  Bottom 0.406: 42.42,12.7 41.15,13.97 33.53,13.97 33.53,11.43
S$61
  Bottom 0.406: 39.88,12.7 36.07,12.7 36.07,11.43
S$62
  Bottom 0.406: 50.04,10.16 51.31,8.89 60.2,8.89 60.2,12.7 56.39,12.7 56.39,11.43
S$63
  Bottom 0.406: 44.96,15.24 43.69,13.97 43.69,11.43
S$64
  Bottom 0.406: 44.96,12.7 44.96,8.89 41.15,8.89 41.15,11.43
S$65
  Bottom 0.406: 42.42,15.24 32.26,15.24 32.26,10.16 37.34,10.16 38.61,11.43
S$66
  Top 0.406: 78.49,7.62 77.22,8.89 69.6,8.89 69.6,6.35
S$67
  Top 0.406: 74.68,6.35 74.68,2.54 78.49,2.54
S$68
  Top 0.406: 83.57,5.08 83.57,3.81 87.38,3.81 87.38,6.35
S$69
  Bottom 0.406: 83.57,15.24 82.3,13.97
S$70
  Bottom 0.406: 79.76,13.97 79.76,11.43 83.57,11.43 83.57,12.7
S$71
  Bottom 0.406: 78.49,15.24 72.14,15.24 72.14,13.97
S$72
  Top 0.406: 81.03,15.24 81.03,16.51 77.22,16.51 77.22,13.97
S$73
  Top 0.406: 81.03,12.7 81.03,11.43 74.68,11.43 74.68,13.97
SCLK
  Bottom 0.406: 88.14,44.58 86.87,44.58 85.6,43.31 83.06,43.31 79.25,39.5 76.71,39.5 75.44,39.5 74.17,40.77 71.63,40.77 67.82,36.96 65.28,36.96 64.01,36.96 62.74,38.23 58.93,38.23 57.66,36.96 53.85,36.96 52.58,36.96 51.31,38.23 47.5,38.23 46.23,36.96 42.42,36.96 41.15,36.96 39.88,35.69 36.07,35.69 34.8,34.42 30.99,34.42 29.72,34.42 28.45,35.69 25.91,35.69 24.64,36.96 20.83,36.96
SDIN
  Bottom 0.406: 88.14,42.04 86.87,42.04 85.6,40.77 83.06,40.77 79.25,36.96 76.71,36.96 75.44,36.96 74.17,38.23 71.63,38.23 67.82,34.42 65.28,34.42 64.01,34.42 62.74,35.69 58.93,35.69 57.66,34.42 53.85,34.42 52.58,34.42 51.31,35.69 47.5,35.69 46.23,34.42 42.42,34.42 41.15,34.42 39.88,33.15 36.07,33.15 34.8,31.88 30.99,31.88 29.72,31.88 28.45,33.15 25.91,33.15 24.64,34.42 23.37,33.15 18.29,33.15 17.02,34.42 13.21,34.42
SDOUT
  Top 0.406: RN6. 25.91,28.07 37.34,28.07 38.61,29.34
  Bottom 0.406: 88.14,36.96 84.33,36.96 81.79,36.96 80.52,35.69 75.44,35.69 74.17,36.96 72.9,36.96 71.63,36.96 67.82,33.15 64.01,33.15 62.74,34.42 61.47,34.42 58.93,34.42 57.66,33.15 52.58,33.15 51.31,34.42 50.04,34.42 47.5,34.42 46.23,33.15 41.15,33.15 39.88,31.88 39.88,30.61 38.61,29.34 | 13.21,31.88 14.48,31.88 18.29,28.07 23.37,28.07 RN6.
SW1
  Top 0.406: 50.09,76.33 50.09,75.11 50.04,73.79 62.61,73.66 C3.
  Bottom 0.406: C3. 64.14,79.88 | 64.14,79.88 64.26,69.98 65.28,69.98 | 64.14,79.88 66.42,79.88
VCC
  Top 0.406: 24.64,47.12 25.91,48.39 25.91,58.55 24.64,59.82
  Bottom 0.406: 55.12,61.09 52.58,61.09 51.31,59.82 GAL5. 47.5,59.82 46.23,61.09 42.42,61.09 37.34,66.17 25.91,66.17 C6. 24.64,59.82 | 55.12,61.09 57.66,61.09 58.93,59.82 GAL4. 62.74,59.82 64.01,61.09 69.09,61.09 70.36,59.82 GAL3. 81.79,59.82 GAL2. 85.6,57.28 86.87,58.55 91.95,58.55 93.22,57.28 GAL1. 95.76,62.36 C5. 93.22,64.9 93.22,68.71 94.49,69.98 94.49,73.79 | 24.64,47.12 25.91,45.85 28.45,45.85 29.72,47.12 30.99,47.12 | 55.12,61.09 55.12,67.44

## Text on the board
Top: 6001 | 22V10 | 20V8 | 16V8 | 18V10 | 26CV12 | 6002 | 20xx10
tPlace: J1
tDocu: 6001 | 22V10 | 20V8 | 16V8 | 18V10 | 26CV12 | 6002 | 20xx10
